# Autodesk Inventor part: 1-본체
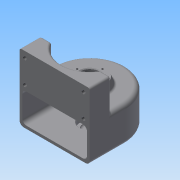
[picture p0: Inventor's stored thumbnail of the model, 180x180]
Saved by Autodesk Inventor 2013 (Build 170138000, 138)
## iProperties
Created: 2011-02
Part Number: 1-본체
Material: 일반
Document SubType Name: Modeling
Designer: Administrator
Density: 1 g/cm^3
Author: Administrator
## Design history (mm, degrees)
sketch "스케치1"
  geometry: L1 (-50, 0)-(-50, -50); L2 (-50, -50)-(50, -50); L3 (50, -50)-(50, 0); A1 r 50 centre (0, 0) between (50, 0) and (-50, 0); 1 further point
  constraints: 6 end point, 2 point on circle, 2 tangent, 1 centre point, 1 coincident, 1 parallel, 1 perpendicular, 1 vertical
  dimensions: "d0" = 50 radius of A1; "d2" = 50 distance from line of L2 point (0, 0)
extrude "돌출1" new body sketch "스케치1" distance "d3" = 50; taper "d4" = 0 deg
feature "쉘1" dims "d5" = 4
sketch "스케치2"
  geometry: C1 r 25 at (0, 0); A1 r 50 centre (0, 0) between (50, 0) and (-50, 0) reference
  constraints: 1 centre point, 1 coincident
  dimensions: "d6" = 50 diameter of C1
extrude "돌출2" join sketch "스케치2" distance "d8" = 10; taper "d9" = -20 deg
hole "구멍1" diameter "d16" = 20; stored, may be unused: countersink angle "d20" = 90 deg, drill point angle "d22" = 118 deg; dims "d14" = 10, "d15" = 10, "d17" = 6, "d18" = 28, "d19" = 10, "d21" = 8
sketch "스케치4"
  geometry: L1 (-50, 0)-(-50, -50) reference; L2 (-50, -50)-(50, -50) reference; L3 (50, -50)-(50, 0) reference; L4 (50, -20)-(34.641, -20); L5 (-34.641, -20)-(-50, -20); A1 r 50 centre (0, 0) between (50, 0) and (-50, 0) reference; A2 r 40 centre (0, 0) between (34.641, -20) and (-34.641, -20)
  constraints: 4 end point, 2 perpendicular, 2 point on circle, 2 point on line, 1 centre point, 1 coincident, 1 collinear
  dimensions: "d32" = 40 radius of A2; "d34" = 30 distance between parallel lines of L2 L4
extrude "돌출4" join sketch "스케치4" distance "d35" = 45; taper "d36" = 0 deg
sketch "스케치5"
  geometry: C1 r 14 at (0, 0) reference; C2 r 21.36 at (0, 0) reference; A1 r 18 centre (0, 0) between (0, 18) and (0, -18); 2 further points
  constraints: 4 point on circle, 2 horizontal alignment, 2 vertical alignment, 1 centre point, 1 coincident
  dimensions: "d37" = 36 diameter of A1
hole "구멍3" sketch "스케치5" at (0, 18), (0, -18), (-18, 0), (18, 0) diameter "d39" = 2.459; stored, may be unused: countersink angle "d43" = 90 deg, drill point angle "d45" = 118 deg; dims "d40" = 6, "d41" = 28, "d42" = 8, "d44" = 9
sketch "스케치6"
  geometry: L1 (100, 0)-(100, 95) reference; L2 (0, 95)-(100, 95) reference; L3 (91, 86)-(7.5, 86); L4 (7.5, 86)-(7.5, 53); L5 (7.5, 53)-(91, 53); L6 (91, 53)-(91, 86); L7 (91, 86)-(7.5, 53); L8 (7.5, 86)-(91, 53); 6 further points
  constraints: 12 end point, 4 coincident, 2 midpoint, 2 parallel, 1 horizontal, 1 perpendicular
  dimensions: "d46" = 33 distance of L5.end L3.start; "d48" = 83.5 distance of L3.start L3.end; "d49" = 9 distance between parallel lines of L2 L3; "d50" = 9 distance between parallel lines of L1 L6
hole "구멍4" sketch "스케치6" at (7.5, 86), (7.5, 53), (91, 86), (91, 53) diameter "d51" = 5.134; stored, may be unused: countersink angle "d55" = 90 deg, drill point angle "d57" = 118 deg; dims "d52" = 10, "d53" = 28, "d54" = 8, "d56" = 13
node "작업 평면1"
sketch "스케치7"
  geometry: L1 (-50, 0)-(50, 0) reference; 3 further points
  constraints: 1 midpoint, 1 vertical alignment, 1 other
  dimensions: "d58" = 25 distance from line of L1 point (0, 25)
feature "엠보싱1" sketch "스케치7" dims "d0" = 50, "d2" = 50, "d59" = 0.5, "d60" = 0
fillet "모깎기1" dims "d61" = 6
fillet "모깎기2" dims "d62" = 3
fillet "모깎기3" dims "d63" = 0.3
fillet "모깎기4" dims "d64" = 3
chamfer "모따기1" distance "d65" = 1; stored, may be unused: second distance "d66" = 2, angle "d67" = 45 deg
sketch "스케치8"
  geometry: C1 r 20 at (0, 0); A1 r 46 centre (0, 0) between (46, 0) and (-46, 0) reference
  constraints: 1 centre point, 1 coincident
  dimensions: "d68" = 40 diameter of C1
extrude "돌출5" join sketch "스케치8" distance "d70" = 13; taper "d71" = 0 deg
sketch "스케치9"
  geometry: C1 r 14 at (0, 0); A1 r 46 centre (0, 0) between (46, 0) and (-46, 0) reference
  constraints: 1 centre point, 1 coincident
  dimensions: "d72" = 28 diameter of C1
extrude "돌출6" cut sketch "스케치9" distance "d74" = 8; taper "d75" = 0 deg
sketch "스케치10"
  geometry: C1 r 14 at (0, 0) reference; C2 r 10 at (0, 0)
  constraints: 1 centre point, 1 coincident
  dimensions: "d76" = 20 diameter of C2
extrude "돌출7" cut sketch "스케치10" distance "d78" = 2; taper "d79" = 0 deg
fillet "모깎기5" dims "d80" = 3
chamfer "모따기2" distance "d81" = 1; stored, may be unused: second distance "d82" = 2, angle "d83" = 45 deg
fillet "모깎기6" dims "d84" = 6
fillet "모깎기7" dims "d85" = 3
node "솔리드1"
